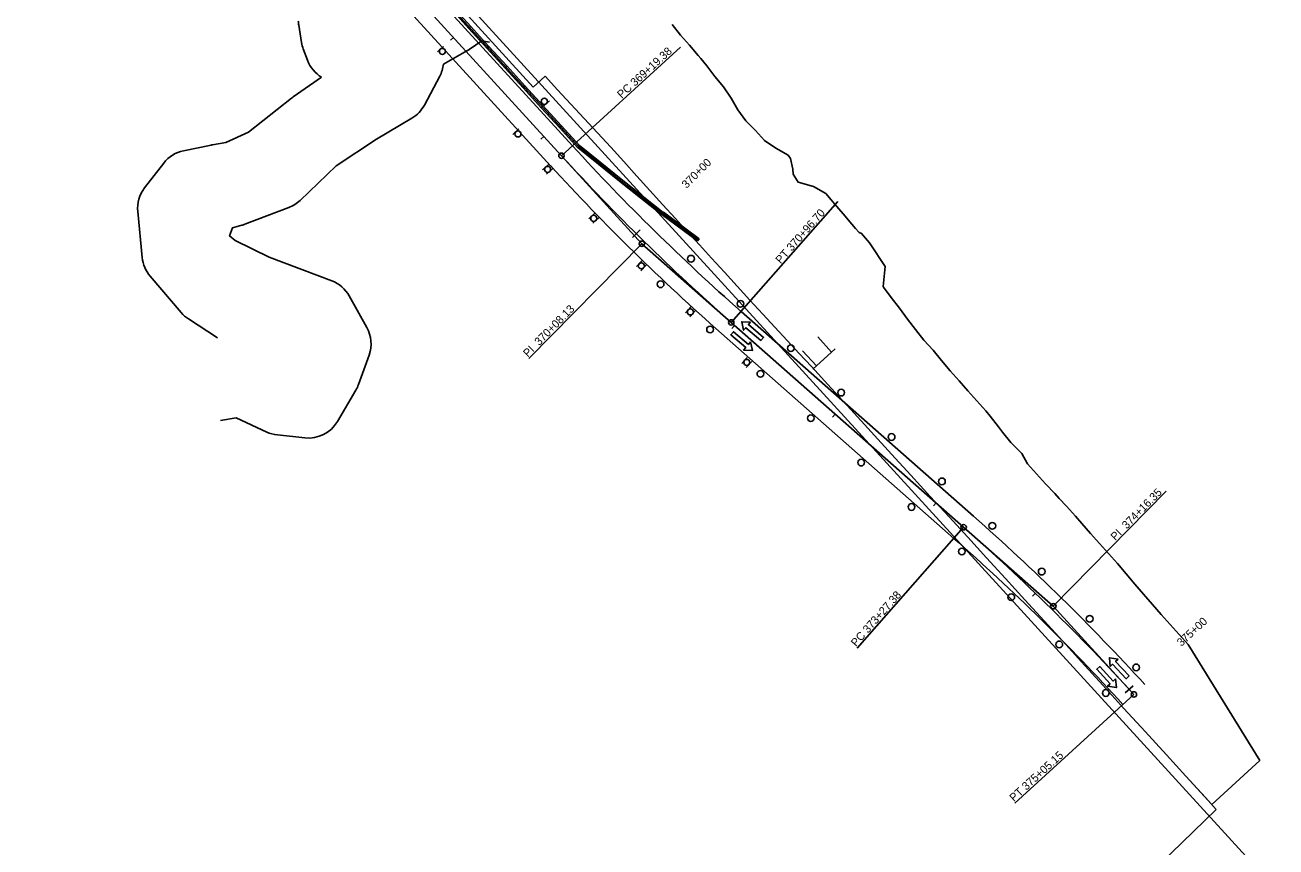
# Model space of a CAD drawing. Extents: x 1193019 to 1196816, y 1474412 to 1477212.
# Drawn here: x 1195206 to 1196137, y 1475404 to 1476016 of the extents above; entities that cross this region are included whole.
import ezdxf

# ---------------------------------------------------------------- set-up
doc = ezdxf.new("R2010")
doc.units = 0
for name, color, linetype in [('R_Draft', 7, 'Continuous'), ('R_Horz Alg', 7, 'Continuous'), ('R_Horz Alg Annot', 7, 'Continuous'), ('R_MOT', 7, 'Continuous'), ('R_No Plot', 7, 'Continuous'), ('R_Striping', 7, 'Continuous'), ('R_Water', 7, 'Continuous')]:
    doc.layers.add(name, color=color, linetype=linetype)

msp = doc.modelspace()

# ---------------------------------------------------------------- linework, layer by layer
at = {"layer": 'R_Draft'}
for p, q in [((1195584.25, 1475970.14), (1195482.86, 1476081.15)), ((1195592.99, 1475978.21), (1195584.25, 1475970.14)), ((1195952.24, 1475689.43), (1195965.74, 1475674.68)), ((1196071.84, 1475554.9), (1196125.41, 1475468.45)), ((1196125.41, 1475468.45), (1196089.6, 1475435.74))]:
    msp.add_line(p, q, dxfattribs=at)
for points in [[(1195687.76, 1476016.69), (1195693.88, 1476008.74), (1195700.64, 1476001.37), (1195707.08, 1475993.71), (1195709.06, 1475991.25), (1195713.4, 1475985.93), (1195719.57, 1475978.03), (1195725.83, 1475970.2), (1195731.61, 1475961.94), (1195736.68, 1475953.02), (1195742.58, 1475944.87), (1195749.63, 1475937.77), (1195756.33, 1475930.34), (1195764.88, 1475924.6), (1195773.96, 1475919.36), (1195775.86, 1475916.83), (1195777.45, 1475909), (1195777.89, 1475905.13), (1195781.53, 1475899.19), (1195792.81, 1475895.94), (1195801.99, 1475890.79), (1195806.01, 1475886.12), (1195808.54, 1475883.23), (1195815.09, 1475875.67), (1195821.5, 1475867.97), (1195824.15, 1475864.88), (1195826.81, 1475861.79), (1195828.73, 1475861.04), (1195834.67, 1475854.17), (1195835.24, 1475853.44), (1195846.22, 1475836.38), (1195845.52, 1475828.97), (1195844.82, 1475821.56), (1195845.13, 1475821.06), (1195850.8, 1475813.48), (1195856.89, 1475805.49), (1195862.81, 1475797.36), (1195868.98, 1475789.45), (1195875.14, 1475781.53), (1195881.92, 1475774.19), (1195888.34, 1475766.51), (1195894.77, 1475758.83), (1195901.35, 1475751.3), (1195907.93, 1475743.77), (1195921.26, 1475728.85), (1195924.4, 1475724.95), (1195930.62, 1475717.09), (1195933.69, 1475713.12), (1195939.98, 1475705.33), (1195948.14, 1475697.15), (1195952.24, 1475689.43)], [(1196089.6, 1475435.74), (1196070.27, 1475456.81), (1196055.67, 1475472.71), (1196039.88, 1475490.04), (1196024.09, 1475507.37), (1196008.3, 1475524.75), (1195992.51, 1475542.13), (1195978.62, 1475557.32), (1195964.73, 1475572.52), (1195950.32, 1475588.29), (1195935.91, 1475604.07), (1195921.84, 1475619.48), (1195907.77, 1475634.89), (1195893.83, 1475650.04), (1195879.88, 1475665.19), (1195865.42, 1475681), (1195850.96, 1475696.81), (1195835.85, 1475713.32), (1195820.75, 1475729.84), (1195806.07, 1475745.87), (1195791.39, 1475761.91), (1195782.34, 1475771.67), (1195773.29, 1475781.44), (1195764.24, 1475791.21), (1195755.2, 1475800.98), (1195745.64, 1475811.37), (1195736.09, 1475821.77), (1195726.53, 1475832.17), (1195716.98, 1475842.56), (1195707.93, 1475852.5), (1195698.88, 1475862.43), (1195689.83, 1475872.36), (1195680.78, 1475882.29), (1195671.06, 1475893.05), (1195661.33, 1475903.82), (1195651.61, 1475914.58), (1195641.89, 1475925.35), (1195632.02, 1475936.02), (1195622.14, 1475946.69), (1195612.26, 1475957.35), (1195602.39, 1475968.02), (1195592.99, 1475978.21)], [(1195965.74, 1475674.68), (1195972.53, 1475667.34), (1195975.92, 1475663.66), (1195981.25, 1475657.89), (1195987.93, 1475650.45), (1195992.69, 1475645.12), (1195999.32, 1475637.64), (1196005.97, 1475630.16), (1196012.61, 1475622.69), (1196019.23, 1475615.19), (1196025.74, 1475607.59), (1196032.22, 1475599.97), (1196038.77, 1475592.41), (1196045.28, 1475584.8), (1196051.9, 1475577.31), (1196058.56, 1475569.85), (1196065.19, 1475562.37), (1196071.84, 1475554.9)]]:
    msp.add_lwpolyline(points, dxfattribs=at)
at = {"layer": 'R_Horz Alg'}
for p, q in [((1195136.65, 1476468.36), (1196620.96, 1474843.25)), ((1195434.62, 1476105.79), (1195605.25, 1475918.98)), ((1195731.68, 1475794.78), (1195904.75, 1475642.27))]:
    msp.add_line(p, q, dxfattribs=at)
for centre, start, end in [((1196813.97, 1477022.98), 222.40729, 228.61356), ((1194822.46, 1474414.06), 42.39163, 48.61356)]:
    msp.add_arc(centre, 1637.02, start, end, dxfattribs=at)
at = {"layer": 'R_Horz Alg Annot'}
for p, q in [((1195605.25, 1475918.98), (1195665.1, 1475853.45)), ((1195665.1, 1475853.45), (1195731.68, 1475794.78)), ((1195904.75, 1475642.27), (1195971.51, 1475583.45)), ((1195971.51, 1475583.45), (1196031.49, 1475517.73))]:
    msp.add_line(p, q, dxfattribs=at)
for points in [[(1195522.52, 1476005.1), (1195524.74, 1476007.13)], [(1195605.25, 1475918.98), (1195693.85, 1475999.91)], [(1195589.96, 1475931.27), (1195592.17, 1475933.29)], [(1195731.68, 1475794.78), (1195811.02, 1475884.81)], [(1195663.88, 1475863.66), (1195658.24, 1475857.98)], [(1195665.1, 1475853.45), (1195581, 1475767.85)], [(1195732.17, 1475790.35), (1195734.15, 1475792.6)], [(1195807.2, 1475724.23), (1195809.18, 1475726.48)], [(1195971.51, 1475583.45), (1196055.61, 1475669.04)], [(1195882.22, 1475658.12), (1195884.21, 1475660.37)], [(1195904.75, 1475642.27), (1195825.42, 1475552.24)], [(1195956.07, 1475590.9), (1195958.15, 1475593.07)], [(1196030.96, 1475524.24), (1196025.06, 1475518.83)], [(1196031.49, 1475517.73), (1195942.86, 1475436.83)]]:
    msp.add_lwpolyline(points, dxfattribs=at)
for centre in [(1195605.25, 1475918.98), (1195665.1, 1475853.45), (1195731.68, 1475794.78), (1195904.75, 1475642.27), (1195971.51, 1475583.45), (1196031.49, 1475517.73)]:
    msp.add_circle(centre, 2, dxfattribs=at)
at = {"layer": 'R_MOT'}
for p, q in [((1195512.89, 1475996.29), (1195517.32, 1476000.34)), ((1195596.22, 1475959.82), (1195591.79, 1475955.77)), ((1195569.11, 1475934.87), (1195573.54, 1475938.92)), ((1195591.19, 1475908.45), (1195595.61, 1475912.5)), ((1195598.65, 1475909.18), (1195594.22, 1475905.13)), ((1195625.56, 1475871.87), (1195629.86, 1475876.05)), ((1195633, 1475872.82), (1195628.7, 1475868.64)), ((1195707.77, 1475857.1), (1195706.48, 1475855.56)), ((1195661.02, 1475836.35), (1195665.2, 1475840.66)), ((1195668.43, 1475837.53), (1195664.26, 1475833.22)), ((1195697.55, 1475801.92), (1195701.59, 1475806.35)), ((1195704.92, 1475803.33), (1195700.88, 1475798.89)), ((1195809.18, 1475775.17), (1195792.53, 1475760.04)), ((1195796.11, 1475784.04), (1195806.44, 1475772.67)), ((1195739.58, 1475764.33), (1195743.62, 1475768.77)), ((1195746.94, 1475765.74), (1195742.9, 1475761.3)), ((1195784.81, 1475773.77), (1195795.14, 1475762.41))]:
    msp.add_line(p, q, dxfattribs=at)
for points in [[(1195617.94, 1475925.84), (1195442.6, 1476117.81)], [(1195617.94, 1475925.84), (1195442.6, 1476117.81)], [(1195706.48, 1475855.56), (1195696.03, 1475863.34), (1195697.23, 1475864.94), (1195707.77, 1475857.1)]]:
    msp.add_lwpolyline(points, dxfattribs=at)
for points in [[(1195524.27, 1476029.88), (1195537.75, 1476015.12), (1195536.28, 1476013.77), (1195522.79, 1476028.53)], [(1195537.75, 1476015.12), (1195551.24, 1476000.35), (1195549.77, 1475999), (1195536.28, 1476013.77)], [(1195551.24, 1476000.35), (1195564.73, 1475985.58), (1195563.25, 1475984.23), (1195549.77, 1475999)], [(1195564.73, 1475985.58), (1195578.22, 1475970.81), (1195576.74, 1475969.46), (1195563.25, 1475984.23)], [(1195578.22, 1475970.81), (1195591.71, 1475956.05), (1195590.23, 1475954.7), (1195576.74, 1475969.46)], [(1195591.71, 1475956.05), (1195605.19, 1475941.28), (1195603.72, 1475939.93), (1195590.23, 1475954.7)], [(1195605.19, 1475941.28), (1195618.68, 1475926.51), (1195617.21, 1475925.16), (1195603.72, 1475939.93)], [(1195618.57, 1475926.62), (1195634.19, 1475914.13), (1195632.94, 1475912.56), (1195617.32, 1475925.06)], [(1195634.19, 1475914.13), (1195649.81, 1475901.63), (1195648.56, 1475900.07), (1195632.94, 1475912.56)], [(1195649.81, 1475901.63), (1195665.42, 1475889.14), (1195664.17, 1475887.58), (1195648.56, 1475900.07)], [(1195665.42, 1475889.14), (1195681.04, 1475876.65), (1195679.79, 1475875.09), (1195664.17, 1475887.58)], [(1195681.18, 1475876.89), (1195697.23, 1475864.94), (1195696.03, 1475863.34), (1195679.99, 1475875.28)]]:
    msp.add_lwpolyline(points, close=True, dxfattribs=at)
for centre, radius in [((1195516.62, 1475996.66), 2.25), ((1195592.49, 1475959.46), 2.25), ((1195572.84, 1475935.23), 2.25), ((1195594.92, 1475908.81), 2.25), ((1195594.92, 1475908.81), 2.25), ((1195629.28, 1475872.35), 2.25), ((1195629.28, 1475872.35), 2.25), ((1195701.72, 1475842.28), 2.5), ((1195664.73, 1475836.94), 2.25), ((1195664.73, 1475836.94), 2.25), ((1195679.06, 1475823.22), 2.5), ((1195701.23, 1475802.62), 2.25), ((1195701.23, 1475802.62), 2.25), ((1195738.54, 1475808.64), 2.5), ((1195715.88, 1475789.58), 2.5), ((1195776.05, 1475775.59), 2.5), ((1195743.26, 1475765.03), 2.25), ((1195743.26, 1475765.03), 2.25), ((1195753.39, 1475756.53), 2.5), ((1195813.56, 1475742.53), 2.5), ((1195790.9, 1475723.47), 2.5), ((1195851.07, 1475709.48), 2.5), ((1195828.41, 1475690.41), 2.5), ((1195888.59, 1475676.42), 2.5), ((1195865.93, 1475657.36), 2.5), ((1195926.08, 1475643.29), 2.5), ((1195903.42, 1475624.22), 2.5), ((1195962.86, 1475609.24), 2.5), ((1195940.2, 1475590.18), 2.5), ((1195998.59, 1475574.1), 2.5), ((1195975.93, 1475555.03), 2.5), ((1196033.24, 1475537.89), 2.5), ((1196010.58, 1475518.82), 2.5)]:
    msp.add_circle(centre, radius, dxfattribs=at)
at = {"layer": 'R_No Plot'}
for p, q in [((1195444.96, 1476115.23), (1195615.58, 1475928.42)), ((1195584.26, 1475970.14), (1195482.87, 1476081.15)), ((1195584.26, 1475970.14), (1195482.87, 1476081.15)), ((1195592.99, 1475978.21), (1195584.26, 1475970.14)), ((1195592.99, 1475978.21), (1195584.26, 1475970.14))]:
    msp.add_line(p, q, dxfattribs=at)
for points in [[(1194926.99, 1476683.64), (1194028.08, 1475811.24), (1195219.02, 1474584.11), (1196092.83, 1475432.14)], [(1194926.99, 1476683.64), (1194028.08, 1475811.24), (1195219.02, 1474584.11), (1196092.83, 1475432.14)], [(1196092.83, 1475432.14), (1196084.86, 1475440.91), (1196070.27, 1475456.81), (1196055.67, 1475472.71), (1196039.88, 1475490.04), (1196024.09, 1475507.37), (1196008.3, 1475524.75), (1195992.51, 1475542.13), (1195978.62, 1475557.32), (1195964.73, 1475572.52), (1195950.32, 1475588.29), (1195935.91, 1475604.07), (1195921.84, 1475619.48), (1195907.77, 1475634.89), (1195893.83, 1475650.04), (1195879.88, 1475665.19), (1195865.42, 1475681), (1195850.96, 1475696.81), (1195835.85, 1475713.32), (1195820.75, 1475729.84), (1195806.07, 1475745.87), (1195791.39, 1475761.91), (1195782.34, 1475771.67), (1195773.29, 1475781.44), (1195764.24, 1475791.21), (1195755.2, 1475800.98), (1195745.64, 1475811.37), (1195736.09, 1475821.77), (1195726.53, 1475832.17), (1195716.98, 1475842.56), (1195707.93, 1475852.5), (1195698.88, 1475862.43), (1195689.83, 1475872.36), (1195680.78, 1475882.29), (1195671.06, 1475893.05), (1195661.33, 1475903.82), (1195651.61, 1475914.58), (1195641.89, 1475925.35), (1195632.02, 1475936.02), (1195622.14, 1475946.69), (1195612.26, 1475957.35), (1195602.39, 1475968.02), (1195592.99, 1475978.21)], [(1196092.83, 1475432.14), (1196084.86, 1475440.91), (1196070.27, 1475456.81), (1196055.67, 1475472.71), (1196039.88, 1475490.04), (1196024.09, 1475507.37), (1196008.3, 1475524.75), (1195992.51, 1475542.13), (1195978.62, 1475557.32), (1195964.73, 1475572.52), (1195950.32, 1475588.29), (1195935.91, 1475604.07), (1195921.84, 1475619.48), (1195907.77, 1475634.89), (1195893.83, 1475650.04), (1195879.88, 1475665.19), (1195865.42, 1475681), (1195850.96, 1475696.81), (1195835.85, 1475713.32), (1195820.75, 1475729.84), (1195806.07, 1475745.87), (1195791.39, 1475761.91), (1195782.34, 1475771.67), (1195773.29, 1475781.44), (1195764.24, 1475791.21), (1195755.2, 1475800.98), (1195745.64, 1475811.37), (1195736.09, 1475821.77), (1195726.53, 1475832.17), (1195716.98, 1475842.56), (1195707.93, 1475852.5), (1195698.88, 1475862.43), (1195689.83, 1475872.36), (1195680.78, 1475882.29), (1195671.06, 1475893.05), (1195661.33, 1475903.82), (1195651.61, 1475914.58), (1195641.89, 1475925.35), (1195632.02, 1475936.02), (1195622.14, 1475946.69), (1195612.26, 1475957.35), (1195602.39, 1475968.02), (1195592.99, 1475978.21)]]:
    msp.add_lwpolyline(points, dxfattribs=at)
msp.add_arc((1196661.51, 1477172.8), 1626.02, 230.0744, 234.05937, dxfattribs=at)
at = {"layer": 'R_Striping'}
for p, q in [((1195442.75, 1476113.21), (1195613.37, 1475926.4)), ((1195434.62, 1476105.79), (1195605.25, 1475918.98)), ((1195426.5, 1476098.37), (1195597.12, 1475911.56)), ((1195738.95, 1475803.03), (1195912.02, 1475650.52)), ((1195731.68, 1475794.78), (1195904.75, 1475642.27)), ((1195724.41, 1475786.52), (1195897.48, 1475634.01))]:
    msp.add_line(p, q, dxfattribs=at)
for points in [[(1195746.08, 1475795.06), (1195739.53, 1475795.35), (1195740.92, 1475788.94), (1195742.53, 1475790.86), (1195753.78, 1475781.37), (1195755.71, 1475783.66), (1195744.47, 1475793.15)], [(1195746.07, 1475780.29), (1195747.43, 1475773.88), (1195740.88, 1475774.2), (1195742.5, 1475776.1), (1195731.3, 1475785.64), (1195733.25, 1475787.92), (1195744.45, 1475778.39)], [(1196019.72, 1475544.03), (1196013.26, 1475545.12), (1196013.85, 1475538.6), (1196015.68, 1475540.29), (1196025.67, 1475529.49), (1196027.87, 1475531.52), (1196017.89, 1475542.33)], [(1196017.88, 1475529.37), (1196018.44, 1475522.84), (1196011.98, 1475523.97), (1196013.83, 1475525.66), (1196003.89, 1475536.51), (1196006.11, 1475538.53), (1196016.04, 1475527.68)]]:
    msp.add_lwpolyline(points, close=True, dxfattribs=at)
for centre, radius, start, end in [((1196813.97, 1477022.98), 1626.02, 222.40729, 228.61356), ((1196813.97, 1477022.98), 1637.02, 222.40729, 228.61356), ((1196813.97, 1477022.98), 1648.02, 222.40729, 228.61356), ((1194822.46, 1474414.06), 1648.02, 42.39163, 48.61356), ((1194822.46, 1474414.06), 1637.02, 42.39163, 48.61356), ((1194822.46, 1474414.06), 1626.02, 42.39163, 48.61356)]:
    msp.add_arc(centre, radius, start, end, dxfattribs=at)
at = {"layer": 'R_Water'}
for p, q in [((1195411.72, 1476003.23), (1195409.59, 1476016.31)), ((1195416.13, 1475990.06), (1195412.98, 1475998.5)), ((1195517.35, 1475987.16), (1195534.81, 1475997.01)), ((1195405.53, 1475962.79), (1195426.64, 1475977.4)), ((1195503.18, 1475956.73), (1195514.58, 1475978.18)), ((1195323.84, 1475922.73), (1195344.37, 1475926.9)), ((1195294.79, 1475895.06), (1195309.03, 1475913.51)), ((1195369.42, 1475867.89), (1195402.13, 1475880.33)), ((1195293.04, 1475843.08), (1195289.69, 1475877.35)), ((1195321.96, 1475802.19), (1195298.88, 1475829.31)), ((1195460.29, 1475791.09), (1195447.22, 1475814.57)), ((1195349.11, 1475783.43), (1195327.45, 1475797.38)), ((1195454.16, 1475748.63), (1195461.98, 1475770.51)), ((1195438.39, 1475721), (1195452.15, 1475744.36)), ((1195393.76, 1475710.98), (1195414.25, 1475708.83))]:
    msp.add_line(p, q, dxfattribs=at)
for points in [[(1195536.58, 1475998.12), (1195546.01, 1476004.53), (1195551.58, 1476003.46)], [(1195345.36, 1475927.08), (1195355.36, 1475928.7), (1195372.08, 1475936.48), (1195404.29, 1475961.87)], [(1195410.58, 1475885.69), (1195437.42, 1475911.51), (1195467.5, 1475931.23), (1195493.92, 1475947)], [(1195434.18, 1475825.81), (1195387.51, 1475843.38), (1195362.29, 1475855.77), (1195358.17, 1475859.23), (1195360.22, 1475865.2), (1195367.3, 1475867.19)], [(1195351.41, 1475721.79), (1195363.09, 1475723.81), (1195385.77, 1475713.2)]]:
    msp.add_lwpolyline(points, dxfattribs=at)
for centre, start, end in [((1195434.26, 1476020.34), 182.73754, 189.26756), ((1195436.4, 1476007.25), 189.26756, 200.49247), ((1195439.55, 1475998.81), 200.49247, 238.9169), ((1195522.52, 1476018.79), 299.43393, 304.21961), ((1195492.5, 1475989.91), 332.01766, 353.69769), ((1195419.76, 1475942.23), 124.69423, 128.24178), ((1195481.11, 1475968.46), 300.83042, 332.01766), ((1195349.35, 1475902.4), 99.18662, 101.4858), ((1195328.82, 1475898.23), 101.4858, 142.32157), ((1195314.57, 1475879.78), 142.32157, 185.58568), ((1195393.25, 1475903.7), 290.8193, 313.90472), ((1195360.54, 1475891.26), 285.69371, 290.8193), ((1195317.93, 1475845.51), 185.58568, 220.39354), ((1195425.38, 1475802.41), 29.09946, 69.37439), ((1195341, 1475818.39), 220.39354, 237.20188), ((1195438.44, 1475778.93), 340.31486, 29.09946), ((1195430.62, 1475757.05), 329.48047, 340.31486), ((1195416.85, 1475733.7), 264.02534, 329.48047), ((1195396.36, 1475735.84), 244.92186, 264.02534)]:
    msp.add_arc(centre, 25, start, end, dxfattribs=at)

# ---------------------------------------------------------------- texts
at = {"layer": 'R_Horz Alg Annot'}
for s, rotation, p in [('PC 369+19.38', 42.40729, (1195650.06, 1475961.27)), ('370+00', 45.22892, (1195698.4, 1475894.2)), ('PT 370+96.70', 48.61356, (1195768.51, 1475838.08)), ('PI  370+08.13', 45.51042, (1195580.29, 1475768.55)), ('PI  374+16.35', 45.5026, (1196017.75, 1475631.93)), ('PC 373+27.38', 48.61356, (1195824.67, 1475552.9)), ('375+00', 42.57193, (1196066.86, 1475553.15)), ('PT 375+05.15', 42.39163, (1195942.19, 1475437.57))]:
    msp.add_text(s, height=6, rotation=rotation, dxfattribs=at).set_placement(p)

doc.saveas('drawing.dxf')
